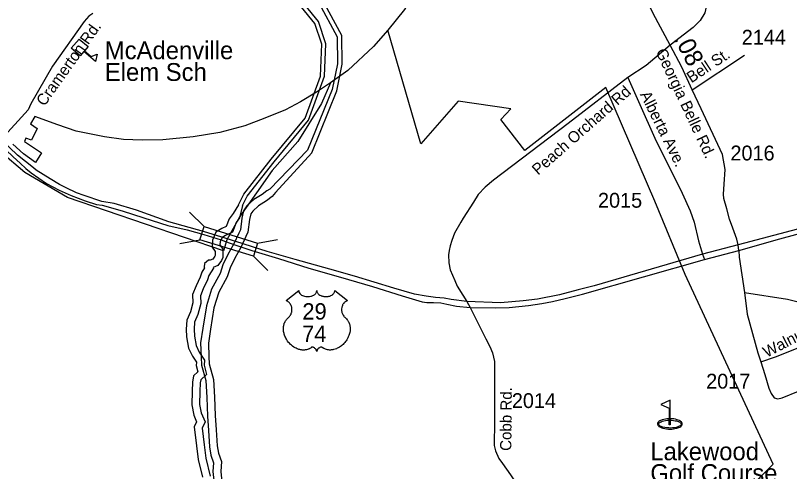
# Model space of a CAD drawing. Extents: x 1364363 to 1407445, y 538563 to 573342.
# Drawn here: x 1379352 to 1385868, y 550075 to 553914 of the extents above; entities that cross this region are included whole.
import ezdxf

# ---------------------------------------------------------------- set-up
doc = ezdxf.new("R2010")
doc.units = 0
for name, color, linetype in [('Exist Boundary Political City Limit New', 7, 'Continuous'), ('Exist Cultural Educational Facility High CELL', 7, 'Continuous'), ('Exist Cultural Educational Facility High Label', 7, 'Continuous'), ('Exist Cultural Recreational Golf Course CELL', 7, 'Continuous'), ('Exist Hydrographic Buffer Line', 7, 'Continuous'), ('Exist Hydrographic Creek Double Shore', 7, 'Continuous'), ('Exist Road Primary US Divided Attributed', 7, 'Continuous'), ('Exist Road Primary US Shield CELL', 7, 'Continuous'), ('Exist Road Primary US Shield Number Label', 7, 'Continuous'), ('Exist Road Primary US Structure Standard Bridge CELL', 7, 'Continuous'), ('Exist Road Secondary Type 51 Attributed', 7, 'Continuous'), ('Exist Road Secondary Type 51 Label', 7, 'Continuous'), ('Exist Road Secondary Type 51 Number Label', 7, 'Continuous')]:
    doc.layers.add(name, color=color, linetype=linetype)

msp = doc.modelspace()

# ---------------------------------------------------------------- linework, layer by layer
at = {"layer": 'Exist Boundary Political City Limit New'}
for points in [[(1383095.2, 555175.1), (1383041, 554870.2), (1382936.2, 554542.2), (1382785.2, 554221.1), (1382626, 553964.3), (1382486.2, 553789.1)], [(1382486.2, 553789.1), (1382365.4, 553653.6), (1382149, 553449.9), (1382004.9, 553346.9)], [(1382486.2, 553789.1), (1382365.4, 553653.6), (1382149, 553449.9), (1382004.9, 553346.9)], [(1386030, 547384.7), (1385702.4, 548024.7), (1385471.1, 548058.8), (1385200.9, 548133.9), (1385014.9, 548190.4), (1384825.6, 548266.9), (1384763.5, 548306.2), (1385007.8, 548489.6), (1384941.6, 548520.2), (1386127.1, 549452.3), (1386509, 549750.2), (1385691.1, 550000.7), (1385605, 550011.1), (1385730.1, 550137), (1384990.9, 551732.2), (1384733.6, 552351.8), (1384320.9, 553308.2), (1383639.1, 552778.5), (1383439.1, 553038.9), (1383521, 553127.3), (1383078.1, 553192.4), (1382763.9, 552834.5), (1382486.2, 553789.1)], [(1382004.9, 553346.9), (1381929.1, 553172.4), (1381728.4, 552852.2), (1381513.1, 552608.7), (1381381.4, 552421.2), (1381242, 552222.3), (1381131.8, 552025.9), (1381103, 551932.9), (1379790.5, 552381.2), (1379430.8, 552591.1), (1379225, 552765.4)], [(1382004.9, 553346.9), (1381885, 553267.3), (1381751.4, 553187.9), (1381625.9, 553120.6), (1381450.4, 553048.1), (1381283, 552985.7), (1381073.6, 552927.9), (1380848.8, 552892.6), (1380592.1, 552867.9), (1380418, 552863.6), (1380262, 552868.8), (1380100.4, 552892.2), (1379863.2, 552939.1), (1379709.2, 552993.7), (1379515.9, 553062.2), (1379479.5, 553001.8), (1379536, 552961.4), (1379487.5, 552862.9), (1379439.9, 552881.9), (1379427.1, 552853.6), (1379572, 552756.5), (1379520.2, 552676.2), (1379420.2, 552749.8), (1379330.5, 552830.2)]]:
    msp.add_lwpolyline(points, dxfattribs=at)
at = {"layer": 'Exist Cultural Educational Facility High CELL'}
msp.add_lwpolyline([(1379888.1, 553715.6), (1379962.9, 553652.4), (1379933.2, 553617.2), (1379990.5, 553568.8), (1380039.4, 553589), (1380025.1, 553526.9), (1379927, 553609.9), (1379897.2, 553574.8), (1379822.5, 553638)], close=True, dxfattribs=at)
at = {"layer": 'Exist Cultural Recreational Golf Course CELL'}
msp.add_lwpolyline([(1384863.8, 550676.6), (1384784.5, 550639.9), (1384854.5, 550609.1), (1384854.5, 550519.7), (1384863.8, 550519.7), (1384863.8, 550507.1), (1384863.8, 550469.6), (1384863.8, 550507.1), (1384875.6, 550506.4), (1384890.8, 550504.7), (1384906.6, 550502.7), (1384917.2, 550500.6), (1384931.1, 550496.4), (1384934.6, 550495.3), (1384945.9, 550489.5), (1384951.9, 550484), (1384954.7, 550479.2), (1384956.2, 550474.4), (1384956, 550472.3), (1384955.5, 550470.2), (1384955, 550468.5), (1384953.9, 550466.7), (1384948.6, 550460.7), (1384940.7, 550456), (1384927, 550450.8), (1384913.7, 550447), (1384896, 550444.3), (1384882.5, 550442.3), (1384862.4, 550441.3), (1384851.2, 550442.3), (1384836.6, 550443), (1384820.1, 550445.3), (1384803.1, 550449), (1384788.6, 550453.3), (1384778.8, 550457.5), (1384772.8, 550462.3), (1384768.6, 550468.3), (1384767.3, 550473.3), (1384768.6, 550478.8), (1384772.1, 550484.3), (1384776.3, 550489.1), (1384780.9, 550491.7), (1384786.6, 550494.6), (1384796.1, 550497.9), (1384809.2, 550501.3), (1384825.6, 550504.3), (1384841.7, 550506.4), (1384854.5, 550507.1), (1384854.5, 550519.7), (1384863.8, 550519.7), (1384863.8, 550469.6), (1384854.5, 550469.6), (1384854.5, 550507.1), (1384854.5, 550519.7), (1384834.3, 550517.8), (1384824.6, 550516.9), (1384809.2, 550513.3), (1384796.4, 550510.2), (1384782.3, 550504.7), (1384776.1, 550501.1), (1384768.2, 550496.2), (1384763, 550490.7), (1384759.9, 550486.6), (1384757.9, 550480.4), (1384757.4, 550475.6), (1384758.8, 550468.3), (1384760.2, 550464.8), (1384764.7, 550458.7), (1384768.8, 550455.2), (1384775.8, 550450.3), (1384781.6, 550447.5), (1384792.9, 550442.7), (1384802.3, 550440.2), (1384817.4, 550436.6), (1384831.5, 550433.8), (1384849.7, 550432.1), (1384861.4, 550431.6), (1384878.3, 550432.6), (1384891, 550433.9), (1384904.2, 550436.2), (1384920.2, 550439.4), (1384935.7, 550444.7), (1384945.4, 550449.7), (1384954.7, 550455.3), (1384959.6, 550460.3), (1384962.6, 550464.4), (1384963.9, 550467.2), (1384964.6, 550469.2), (1384965.3, 550472.4), (1384965.7, 550475.8), (1384964.9, 550481.4), (1384962.7, 550486.6), (1384957.7, 550492.9), (1384954.6, 550496.3), (1384947.2, 550501.2), (1384941.3, 550504.5), (1384931, 550508.8), (1384923.8, 550510.8), (1384907.3, 550515.2), (1384893.5, 550517.7), (1384863.8, 550519.7)], close=True, dxfattribs=at)
at = {"layer": 'Exist Hydrographic Buffer Line'}
for points in [[(1381612, 554942.3), (1381734.6, 554699.8), (1381883.4, 554428.4), (1381901.8, 554156.3), (1381899.8, 554039.9), (1381904.7, 554020.1), (1382060, 553733.4), (1382063.7, 553508), (1382018.4, 553290.2), (1381811.7, 552779.8), (1381494.1, 552450.5)], [(1381952.6, 553402.4), (1381963.8, 553676.1), (1381903, 553863.3), (1381616.3, 554216.5), (1381504.1, 554587.1)], [(1381263.6, 552315.6), (1381302.7, 552393.3), (1381529, 552682.4), (1381818.8, 553032.2), (1381952.6, 553402.4)], [(1381494.1, 552450.5), (1381468.4, 552438.6), (1381428.2, 552407.6), (1381358.3, 552365), (1381300.5, 552310.2), (1381271.7, 552270.1), (1381258.8, 552207.7), (1381245.9, 552109.6), (1381232.2, 552080.6), (1381190.7, 551990.8), (1381139.5, 551901.5), (1381099.1, 551814.4), (1381074.1, 551740.6), (1381002.8, 551609.6), (1380959.5, 551468.6), (1380928.5, 551282.9), (1380910.9, 551159.4), (1380914.5, 551039.2), (1380918.2, 550971.2), (1380953.5, 550840.2), (1380961.9, 550697.1), (1380968.7, 550542.5), (1380976.3, 550421.7), (1380985.7, 550283.4), (1380997.9, 550213.1), (1381019.8, 550149.7), (1381014.4, 550075.5), (1381025.7, 549977.9)], [(1381263.6, 552315.6), (1381238.6, 552211.5), (1381209.1, 552170.2), (1381179.3, 552089.2), (1381120.9, 552062.6), (1381091.6, 552045), (1381075, 552008), (1381073.6, 551983.2), (1381099.1, 551948), (1381099.1, 551877.8), (1381086.6, 551852.6), (1381056.2, 551810.1), (1381015.1, 551792.4), (1381018.5, 551785.6), (1380979.5, 551724.3), (1380967.6, 551688.5), (1380933.3, 551612.9), (1380909.1, 551553.9), (1380912.3, 551488.1), (1380888.4, 551397.1), (1380860.5, 551331.8), (1380855.2, 551273.2), (1380858.1, 551215), (1380872.4, 551134.7), (1380899.8, 551079.9), (1380944.2, 551013.3), (1380939.5, 550971.1), (1380959.6, 550891), (1380911.7, 550847.4), (1380908.3, 550820.5), (1380905.1, 550750.1), (1380902, 550640.7), (1380916, 550567.9), (1380948.3, 550494.1), (1380923.7, 550440.8), (1380941.5, 550298.6), (1380954.4, 550188.6), (1380991.9, 550036.7)]]:
    msp.add_lwpolyline(points, dxfattribs=at)
at = {"layer": 'Exist Hydrographic Creek Double Shore'}
for points in [[(1381919.8, 553403.7), (1381930.8, 553671.6), (1381873.7, 553847.4), (1381586.8, 554200.8), (1381491.2, 554483)], [(1381919.8, 553403.7), (1381930.8, 553671.6), (1381873.7, 553847.4), (1381586.8, 554200.8), (1381491.2, 554483)], [(1381541.6, 552424), (1381845.8, 552757.6), (1382056.8, 553278.6), (1382103.8, 553504.1), (1382099.8, 553743.8), (1381939.8, 554039.2), (1381941.9, 554157.3)], [(1381229.6, 552320.9), (1381274.8, 552411), (1381503.4, 552703), (1381789.9, 553048.8), (1381919.8, 553403.7)], [(1381541.6, 552424), (1381514.2, 552391), (1381465.4, 552353.5), (1381398.4, 552312.6), (1381350.2, 552266.9), (1381333.2, 552243.1), (1381323.5, 552196.7), (1381309.6, 552090.9), (1381291.6, 552052.9), (1381249.1, 551960.6), (1381197.8, 551871.3), (1381160.1, 551790), (1381134.5, 551714.2), (1381063.6, 551584), (1381023.5, 551453.5), (1380993.4, 551272.8), (1380976.7, 551155.7), (1380980, 551041.9), (1380983.4, 550981.7), (1381018.6, 550850.8), (1381027.4, 550700.4), (1381034.2, 550546), (1381041.8, 550426), (1381050.9, 550291.3), (1381061.7, 550229.5), (1381086.3, 550158.4), (1381080.3, 550076.9), (1381090.4, 549989.8)], [(1381229.6, 552320.9), (1381184, 552248), (1381150.6, 552201.1), (1381127.2, 552137.5), (1381090.4, 552120.8), (1381040.2, 552090.7), (1381010.1, 552023.8), (1381006.8, 551963.5), (1381033.5, 551926.7), (1381033.5, 551893.2), (1381030.2, 551886.6), (1381013.5, 551863.1), (1380990, 551853.1), (1380976.7, 551853.1), (1380943.2, 551826.3), (1380939.9, 551796.2), (1380943.2, 551789.5), (1380919.8, 551752.7), (1380906.4, 551712.5), (1380873, 551638.9), (1380842.9, 551565.3), (1380846.3, 551495), (1380826.2, 551418.4), (1380796.1, 551348.1), (1380789.4, 551274.5), (1380792.8, 551207.6), (1380809.5, 551113.9), (1380842.9, 551047), (1380876.4, 550996.8), (1380873, 550966.6), (1380886.4, 550913.1), (1380849.6, 550879.6), (1380842.9, 550826.1), (1380839.6, 550752.5), (1380836.2, 550635.4), (1380852.9, 550548.4), (1380876.4, 550494.8), (1380856.3, 550451.3), (1380876.4, 550290.7), (1380889.7, 550176.9), (1380926.5, 550027.7)]]:
    msp.add_lwpolyline(points, dxfattribs=at)
at = {"layer": 'Exist Road Primary US Divided Attributed'}
msp.add_line((1385436.5, 551983), (1385135.5, 551904.4), dxfattribs=at)
for points in [[(1379202.8, 552844.1), (1379332.7, 552724.3), (1379390.5, 552671.5), (1379438.4, 552626.5), (1379483.4, 552590.6), (1379612.2, 552500.6), (1379720.1, 552443.7), (1379822, 552398.7), (1379938.8, 552353.7), (1380034.7, 552323.7), (1380083.1, 552316.1), (1380250.9, 552268.2), (1380433.3, 552209.8), (1380634, 552146.3), (1380798.3, 552110.5), (1380938.3, 552069.4), (1381083.1, 552026), (1381119.4, 552012.7)], [(1381125.6, 552035.3), (1380934.6, 552096), (1380642.8, 552176.1), (1380369.8, 552273.8), (1380183.4, 552330.8), (1380079.2, 552348.8), (1379929.3, 552399.7), (1379866.4, 552420.7), (1379779.5, 552462.7), (1379722.6, 552489.7), (1379644.7, 552537.7), (1379527.8, 552612.6), (1379503.8, 552630.6), (1379369, 552738.5), (1379231.5, 552868.9)], [(1386429.2, 552257.7), (1386220.5, 552198.4), (1386085.2, 552155), (1385436.5, 551983)], [(1385442.2, 551934.3), (1385787.9, 552033.7), (1386234, 552154.3), (1386438.6, 552212.8)], [(1381119.4, 552012.7), (1381198.9, 551983.4), (1381275.2, 551958.7), (1381342.4, 551935.8), (1381565.2, 551867.4), (1381820.7, 551786.6), (1382089, 551710.3), (1382358, 551632.4), (1382608.1, 551553.1), (1382775.8, 551503.9), (1382815.1, 551498.8), (1382870.4, 551498.1), (1382931.7, 551494.4), (1382984.7, 551484.8), (1383066, 551465.7), (1383181, 551455.5)], [(1383152.5, 551505.5), (1383021, 551522.3), (1382962, 551534), (1382889.3, 551539.9), (1382809.1, 551550.2), (1382710.7, 551569.3), (1382538.1, 551619.2), (1382205.9, 551720.5), (1381997.8, 551779.3), (1381707.1, 551858.6), (1381471.8, 551926.1), (1381355.1, 551963.7), (1381259.8, 551993.7), (1381125.6, 552035.3)], [(1385153.6, 551858.9), (1385442.2, 551934.3)], [(1385135.5, 551904.4), (1384225.1, 551639), (1384090.4, 551603.8), (1383930.7, 551561.2), (1383746.1, 551526), (1383625.7, 551512.7), (1383436.5, 551495.1), (1383152.5, 551505.5)], [(1383181, 551455.5), (1383389.6, 551454), (1383507.6, 551456.9), (1383671.9, 551471.6), (1383782.4, 551490.7), (1383873.2, 551506.9), (1383980.7, 551530.4), (1384126.7, 551567.1), (1385153.6, 551858.9)]]:
    msp.add_lwpolyline(points, dxfattribs=at)
at = {"layer": 'Exist Road Primary US Shield CELL'}
msp.add_lwpolyline([(1381736.5, 551598.5), (1381736.8, 551594.1), (1381737.9, 551588.9), (1381738.7, 551586.2), (1381741.1, 551581), (1381745.2, 551574.9), (1381750.8, 551569), (1381757.1, 551563.7), (1381761.4, 551561), (1381768.6, 551557.1), (1381776.9, 551553.6), (1381786, 551551), (1381795.4, 551549.1), (1381805.6, 551548), (1381815.7, 551547.8), (1381826.6, 551548.6), (1381838.7, 551550.9), (1381844.3, 551552.4), (1381850.5, 551554.5), (1381856.3, 551556.9), (1381862.6, 551560.3), (1381867.7, 551563.6), (1381871.7, 551566.4), (1381877.3, 551571.8), (1381881.8, 551577.4), (1381883.7, 551580.6), (1381885.3, 551583.6), (1381887.5, 551590), (1381888.2, 551592.8), (1381888.6, 551598.7), (1381889, 551593.8), (1381889.5, 551590.7), (1381890.3, 551587.7), (1381891.6, 551584.5), (1381893.8, 551579.9), (1381896.3, 551576.2), (1381901.1, 551570.6), (1381904, 551567.8), (1381906.7, 551565.6), (1381913.9, 551560.7), (1381922.4, 551556.4), (1381926.5, 551554.6), (1381930.8, 551553.1), (1381936.2, 551551.4), (1381941.8, 551550.1), (1381947.3, 551549.2), (1381953, 551548.4), (1381958.7, 551547.9), (1381963.4, 551547.8), (1381969.2, 551547.9), (1381974.5, 551548.2), (1381980, 551548.8), (1381986, 551549.8), (1381990.9, 551550.9), (1381997.3, 551552.6), (1382003, 551554.6), (1382008.1, 551556.8), (1382014.7, 551560.3), (1382020, 551563.6), (1382023.9, 551566.8), (1382028.6, 551571), (1382033, 551576.1), (1382035.6, 551579.8), (1382037.4, 551583.7), (1382039.1, 551587.7), (1382040.1, 551591.9), (1382040.6, 551595.6), (1382040.7, 551598.8), (1382147, 551514.1), (1382144.5, 551513.2), (1382138.7, 551510.4), (1382134.1, 551507.7), (1382126.8, 551502.5), (1382123.7, 551499.7), (1382120.5, 551496.7), (1382117.7, 551493.6), (1382115.1, 551490.6), (1382112, 551486.4), (1382109.3, 551482.1), (1382106.6, 551477.4), (1382104.6, 551473.3), (1382101.3, 551464.8), (1382099.8, 551459.4), (1382098.8, 551454.8), (1382097.5, 551445.3), (1382097.2, 551440.8), (1382097.2, 551436.3), (1382097.4, 551431.6), (1382097.9, 551427.1), (1382098.7, 551422.4), (1382099.4, 551418.2), (1382100.8, 551413.2), (1382102.6, 551407.3), (1382105, 551401.5), (1382109.8, 551392.3), (1382116.1, 551382.9), (1382120.5, 551377.6), (1382124.9, 551373.1), (1382131.5, 551367.6), (1382135, 551364.4), (1382139.1, 551360.3), (1382145.8, 551352.6), (1382148.5, 551349), (1382151.2, 551344.9), (1382153.7, 551340.7), (1382156.2, 551336.2), (1382158.2, 551332.2), (1382162, 551323.1), (1382164.7, 551314.2), (1382165.9, 551309.6), (1382167.9, 551299.2), (1382168.7, 551294), (1382169.5, 551283.8), (1382169.5, 551271.5), (1382168.6, 551259.9), (1382166.4, 551246.2), (1382164.6, 551238.1), (1382161.8, 551228.6), (1382159.1, 551220.4), (1382154.2, 551208.2), (1382149.9, 551199.4), (1382144.3, 551189.1), (1382140.5, 551182.9), (1382136, 551176.3), (1382130.5, 551168.6), (1382123.9, 551160.4), (1382116.1, 551151.8), (1382109.7, 551145.5), (1382101.5, 551138.1), (1382096.4, 551133.9), (1382089.3, 551128.5), (1382079.5, 551122), (1382069.8, 551116.4), (1382061.6, 551112.2), (1382054.3, 551109.1), (1382044.9, 551105.5), (1382029.2, 551101.2), (1382023.5, 551100), (1382016.7, 551099), (1382010.4, 551098.3), (1382004.2, 551098), (1381995.9, 551098), (1381987.7, 551098.6), (1381979.9, 551099.7), (1381971.8, 551101.4), (1381963.4, 551103.9), (1381955.7, 551106.9), (1381947.9, 551110.8), (1381934.7, 551119.1), (1381931, 551121.1), (1381928.8, 551121.6), (1381923.7, 551121.9), (1381919, 551120.9), (1381914.1, 551118.9), (1381911.1, 551117.4), (1381907.2, 551114.8), (1381904.2, 551112.4), (1381900.5, 551109), (1381898, 551106.1), (1381896.1, 551103.8), (1381892.4, 551098), (1381891.1, 551095.2), (1381889.7, 551091.6), (1381888.5, 551086.4), (1381886.8, 551093), (1381884.9, 551097.4), (1381882.6, 551101.2), (1381880.3, 551104.5), (1381876.6, 551108.8), (1381873.2, 551112), (1381869.2, 551115.2), (1381865, 551117.8), (1381861.5, 551119.6), (1381858.4, 551120.8), (1381854.6, 551121.7), (1381851.4, 551122), (1381848.9, 551121.9), (1381845.3, 551121.1), (1381840.5, 551117.6), (1381836, 551114.5), (1381831, 551111.4), (1381825.1, 551108.3), (1381820.8, 551106.3), (1381815.6, 551104.2), (1381809.6, 551102.2), (1381803.1, 551100.5), (1381796.3, 551099.2), (1381790.4, 551098.3), (1381784.1, 551097.7), (1381778.4, 551097.5), (1381772.4, 551097.6), (1381766.8, 551098), (1381760.4, 551098.6), (1381752.3, 551099.8), (1381745.7, 551101.3), (1381738.7, 551103.2), (1381731.4, 551105.4), (1381723.7, 551108.4), (1381714.1, 551112.6), (1381707.3, 551116.1), (1381696.7, 551122.1), (1381684.3, 551130.7), (1381674.9, 551138.3), (1381668.1, 551144.6), (1381658, 551154.9), (1381652, 551161.6), (1381642.7, 551173.6), (1381636.7, 551182.4), (1381632.9, 551188.8), (1381627.2, 551199.1), (1381624.1, 551205.5), (1381620.1, 551215), (1381616.9, 551223.6), (1381614.3, 551231.7), (1381612.9, 551236.9), (1381610.9, 551246), (1381609.7, 551252.5), (1381608.5, 551261.4), (1381607.8, 551270.7), (1381607.7, 551279.3), (1381607.9, 551286.5), (1381608.7, 551294.8), (1381610.1, 551303.7), (1381611.8, 551311.3), (1381613.4, 551316.8), (1381615.6, 551323.4), (1381618.6, 551330.8), (1381622.1, 551337.8), (1381625.5, 551343.6), (1381629.7, 551349.9), (1381633.8, 551355.3), (1381639.2, 551361.2), (1381644.9, 551366.6), (1381650.1, 551370.8), (1381656.2, 551376.8), (1381659.4, 551380.4), (1381663.3, 551385.5), (1381666.4, 551390.2), (1381668.8, 551394.4), (1381672, 551400.7), (1381674, 551405.3), (1381676.4, 551412.5), (1381677.7, 551417.5), (1381678.9, 551424), (1381679.7, 551430), (1381680, 551437.6), (1381679.9, 551443.9), (1381679, 551451.3), (1381677.7, 551458.3), (1381676, 551464.5), (1381673.4, 551471.5), (1381670.9, 551476.6), (1381666.9, 551483.6), (1381662.3, 551490.1), (1381657.7, 551495.4), (1381653, 551500.1), (1381648.4, 551503.6), (1381644.1, 551506.7), (1381638.7, 551509.9), (1381633.5, 551512.5), (1381630.3, 551513.8)], close=True, dxfattribs=at)
at = {"layer": 'Exist Road Primary US Structure Standard Bridge CELL'}
for p, q in [((1380817.9, 552257.4), (1380939.5, 552136.3)), ((1380736.8, 551993.8), (1380905.5, 552025.6)), ((1381388.9, 551997.4), (1381557.5, 552029.3)), ((1381355.6, 551889.2), (1381477.2, 551768.1))]:
    msp.add_line(p, q, dxfattribs=at)
msp.add_lwpolyline([(1380939.5, 552136.3), (1381389, 551997.9), (1381355, 551887.3), (1380905.5, 552025.6)], close=True, dxfattribs=at)
at = {"layer": 'Exist Road Secondary Type 51 Attributed'}
msp.add_line((1385049.2, 553287.6), (1385489, 553579.8), dxfattribs=at)
for points in [[(1385203.6, 554513), (1385189.2, 554157.2), (1385176.5, 554023.4), (1385154.7, 553935.8), (1385117.4, 553872.6), (1385056, 553813.8), (1384864.9, 553663.7)], [(1384864.9, 553663.7), (1384721.7, 553929.8), (1384562.1, 554257.3)], [(1380003.9, 553931.4), (1379969.2, 553908.8), (1379931.5, 553863.5), (1379663, 553486.2), (1379481.9, 553169.5), (1379460.5, 553120.6), (1379231.5, 552868.9)], [(1384864.9, 553663.7), (1384662.5, 553492.7), (1384507, 553391)], [(1385049.2, 553287.6), (1384961, 553477.5), (1384864.9, 553663.7)], [(1384507, 553391), (1384004.7, 553003.1), (1383377.7, 552526.5), (1383305.5, 552469.5), (1383248.1, 552406.5), (1383207.9, 552341), (1383121.8, 552207.2), (1383101.1, 552173.6), (1383047.5, 552081.1), (1383024.8, 552020.9), (1383012.7, 551975.3), (1383002.1, 551934.2), (1382998.3, 551899), (1383001.3, 551831.4), (1383010.4, 551772.7), (1383051.9, 551684.3), (1383069.9, 551636), (1383117.4, 551560.9), (1383152.5, 551505.5)], [(1384507, 553391), (1384608.8, 553164.8), (1384734.7, 552881.8), (1384965.5, 552416.8), (1385031, 552269.6), (1385064.7, 552173.3), (1385103.2, 552016.8), (1385117.6, 551961.5), (1385135.5, 551904.4)], [(1385436.5, 551983), (1385424.5, 552031.5), (1385391.4, 552122.2), (1385364, 552199.6), (1385339.5, 552286.4), (1385316.1, 552373.7), (1385313.7, 552409.5), (1385318.5, 552493), (1385327, 552616.3), (1385305.3, 552743.9), (1385123.8, 553128.1), (1385049.2, 553287.6)], [(1385442.2, 551934.3), (1385436.5, 551983)], [(1385442.2, 551934.3), (1385444.2, 551879.1), (1385490, 551582)], [(1385135.5, 551904.4), (1385153.6, 551858.9)], [(1385490, 551582), (1385852, 551524.8), (1385930.7, 551505.7), (1385983.1, 551493.8), (1386054.8, 551484.3), (1386099.9, 551493.8), (1386157, 551522.4), (1386184.7, 551546.3), (1386232.4, 551589.2), (1386282.4, 551632.1), (1386390.8, 551718)], [(1385625.7, 550999.2), (1385750.9, 551040), (1385968.4, 551128.7), (1386074.3, 551184), (1386192.1, 551232.2), (1386346.1, 551302), (1386427.9, 551333.3), (1386466.4, 551350.2), (1386476, 551371.8), (1386480.9, 551386.3), (1386468.8, 551453.7), (1386456.8, 551494.6), (1386390.8, 551718)], [(1385490, 551582), (1385511.3, 551400.7), (1385600.3, 551073.3), (1385625.7, 550999.2)], [(1383152.5, 551505.5), (1383181, 551455.5)], [(1383181, 551455.5), (1383208.3, 551400.4), (1383264.7, 551286.6), (1383313.1, 551192.6), (1383346.4, 551127.2), (1383369.2, 551072.9), (1383384.3, 551002.4), (1383385.7, 550655), (1383384.3, 550497.2), (1383382.8, 550293.1), (1383393.3, 550250.6), (1383422.1, 550185.9), (1383450.9, 550143.3), (1383519, 550046.4), (1383624.2, 549890.7), (1383687, 549774.7), (1383755.1, 549642.5), (1383799.8, 549558.8), (1383825.5, 549488.3), (1383840.7, 549420.8), (1383845.2, 549354.7), (1383823.8, 549043.7)], [(1385625.7, 550999.2), (1385660.4, 550892.7), (1385694.1, 550776.9), (1385713.4, 550731.2), (1385739.8, 550695.6), (1385768.7, 550688.3), (1385807.2, 550695.6), (1385944.3, 550750.9)]]:
    msp.add_lwpolyline(points, dxfattribs=at)

# ---------------------------------------------------------------- texts
at = {"layer": 'Exist Cultural Educational Facility High Label'}
for s, p in [('McAdenville', (1380104.5, 553545.7)), ('Elem Sch', (1380104.5, 553362.9))]:
    msp.add_text(s, height=150, dxfattribs=at).set_placement(p)
at = {"layer": 'Exist Cultural Recreational Golf Course CELL'}
for s, p in [('Lakewood', (1384696.8, 550170.3)), ('Golf Course', (1384696.8, 549987.5))]:
    msp.add_text(s, height=150, dxfattribs=at).set_placement(p)
at = {"layer": 'Exist Road Primary US Shield Number Label'}
for s, p in [('29', (1381767.5, 551354.4)), ('74', (1381765.3, 551166.5))]:
    msp.add_text(s, height=137.5, dxfattribs=at).set_placement(p)
at = {"layer": 'Exist Road Secondary Type 51 Attributed'}
msp.add_text('.08', height=150, rotation=297.29539, dxfattribs=at).set_placement((1384892.4, 553719.4))
at = {"layer": 'Exist Road Secondary Type 51 Label'}
for s, rotation, p in [('Cramerton Rd.', 54.56178, (1379596.3, 553143.8)), ('Georgia Belle Rd.', 295.06229, (1384739.6, 553609.2)), ('Bell St.', 33.59453, (1385042.2, 553342.1)), ('Peach Orchard Rd', 41.29693, (1383751.5, 552564.7)), ('Alberta Ave.', 296.40097, (1384607.2, 553249.3)), ('Walnut Ave.', 27.61304, (1385676.2, 551031.4)), ('Cobb Rd.', 89.50286, (1383526.4, 550248.8))]:
    msp.add_text(s, height=95, rotation=rotation, dxfattribs=at).set_placement(p)
at = {"layer": 'Exist Road Secondary Type 51 Number Label'}
for s, p in [('2144', (1385466.4, 553668)), ('2016', (1385370.9, 552693.5)), ('2015', (1384256.1, 552295.8)), ('2017', (1385166.6, 550773.2)), ('2014', (1383530.8, 550609.7))]:
    msp.add_text(s, height=125, dxfattribs=at).set_placement(p)

doc.saveas('drawing.dxf')
